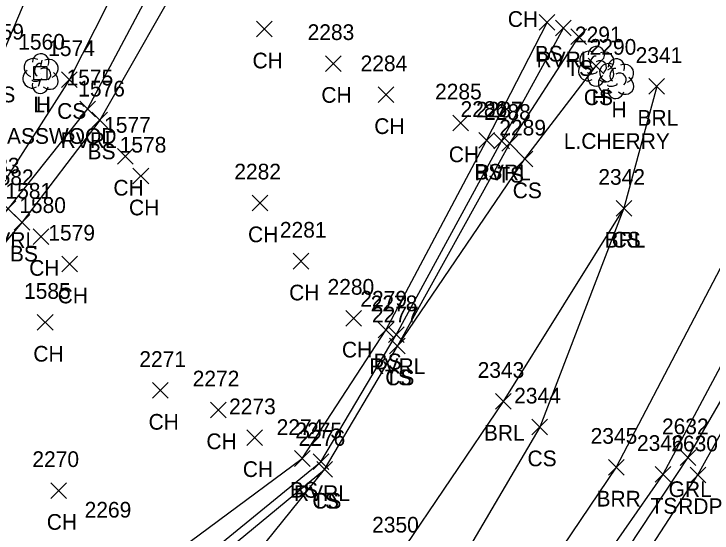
# Model space of a CAD drawing. Extents: x 1504228 to 1506103, y 437717 to 440106.
# Drawn here: x 1505331 to 1505420, y 438222.5 to 438288.7 of the extents above; entities that cross this region are included whole.
import ezdxf

# ---------------------------------------------------------------- set-up
doc = ezdxf.new("R2010")
doc.units = 0
for name, color, linetype in [('L_A', 7, 'Continuous'), ('L_C', 7, 'Continuous'), ('L_I', 7, 'Continuous'), ('L_TIC', 7, 'Continuous'), ('LABL', 7, 'Continuous'), ('LAWE', 7, 'Continuous'), ('LELB', 7, 'Continuous'), ('LTD', 7, 'Continuous'), ('P_A', 7, 'Continuous'), ('P_I', 7, 'Continuous'), ('P_TIC', 7, 'Continuous'), ('PET', 7, 'Continuous'), ('R_A', 7, 'Continuous'), ('R_I', 7, 'Continuous'), ('R_TIC', 7, 'Continuous'), ('RGR', 7, 'Continuous'), ('U_A', 7, 'Continuous'), ('U_I', 7, 'Continuous'), ('ULP', 7, 'Continuous')]:
    doc.layers.add(name, color=color, linetype=linetype)

msp = doc.modelspace()

# ---------------------------------------------------------------- linework, layer by layer
at = {"layer": 'L_TIC'}
for points in [[(1505397.951, 438286.599), (1505399.951, 438288.599)], [(1505399.951, 438286.599), (1505397.951, 438288.599)], [(1505400.036, 438285.88), (1505402.036, 438287.88)], [(1505402.036, 438285.88), (1505400.036, 438287.88)], [(1505361.905, 438285.738), (1505363.905, 438287.738)], [(1505363.905, 438285.738), (1505361.905, 438287.738)], [(1505402.001, 438284.772), (1505404.001, 438286.772)], [(1505404.001, 438284.772), (1505402.001, 438286.772)], [(1505370.679, 438281.353), (1505372.679, 438283.353)], [(1505372.679, 438281.353), (1505370.679, 438283.353)], [(1505404.197, 438281.056), (1505406.197, 438283.056)], [(1505406.197, 438281.056), (1505404.197, 438283.056)], [(1505337.033, 438279.312), (1505339.033, 438281.312)], [(1505339.033, 438279.312), (1505337.033, 438281.312)], [(1505411.94, 438278.434), (1505413.94, 438280.434)], [(1505413.94, 438278.434), (1505411.94, 438280.434)], [(1505377.43, 438277.375), (1505379.43, 438279.375)], [(1505379.43, 438277.375), (1505377.43, 438279.375)], [(1505339.369, 438275.571), (1505341.369, 438277.571)], [(1505341.369, 438275.571), (1505339.369, 438277.571)], [(1505340.915, 438274.153), (1505342.915, 438276.153)], [(1505342.915, 438274.153), (1505340.915, 438276.153)], [(1505386.933, 438273.784), (1505388.933, 438275.784)], [(1505388.933, 438273.784), (1505386.933, 438275.784)], [(1505390.234, 438271.553), (1505392.234, 438273.553)], [(1505392.234, 438271.553), (1505390.234, 438273.553)], [(1505392.16, 438271.478), (1505394.16, 438273.478)], [(1505394.16, 438271.478), (1505392.16, 438273.478)], [(1505393.187, 438271.178), (1505395.187, 438273.178)], [(1505395.187, 438271.178), (1505393.187, 438273.178)], [(1505344.162, 438269.531), (1505346.162, 438271.531)], [(1505346.162, 438269.531), (1505344.162, 438271.531)], [(1505395.131, 438269.191), (1505397.131, 438271.191)], [(1505397.131, 438269.191), (1505395.131, 438271.191)], [(1505346.151, 438267.009), (1505348.151, 438269.009)], [(1505348.151, 438267.009), (1505346.151, 438269.009)], [(1505329.226, 438262.864), (1505331.226, 438264.864)], [(1505331.226, 438262.864), (1505329.226, 438264.864)], [(1505361.331, 438263.585), (1505363.331, 438265.585)], [(1505363.331, 438263.585), (1505361.331, 438265.585)], [(1505407.751, 438262.902), (1505409.751, 438264.902)], [(1505409.751, 438262.902), (1505407.751, 438264.902)], [(1505407.751, 438262.902), (1505409.751, 438264.902)], [(1505409.751, 438262.902), (1505407.751, 438264.902)], [(1505331.016, 438261.134), (1505333.016, 438263.134)], [(1505333.016, 438261.134), (1505331.016, 438263.134)], [(1505333.424, 438259.308), (1505335.424, 438261.308)], [(1505335.424, 438259.308), (1505333.424, 438261.308)], [(1505337.055, 438255.79), (1505339.055, 438257.79)], [(1505339.055, 438255.79), (1505337.055, 438257.79)], [(1505366.575, 438256.169), (1505368.575, 438258.169)], [(1505368.575, 438256.169), (1505366.575, 438258.169)], [(1505373.306, 438248.895), (1505375.306, 438250.895)], [(1505375.306, 438248.895), (1505373.306, 438250.895)], [(1505333.952, 438248.367), (1505335.952, 438250.367)], [(1505335.952, 438248.367), (1505333.952, 438250.367)], [(1505377.412, 438247.378), (1505379.412, 438249.378)], [(1505379.412, 438247.378), (1505377.412, 438249.378)], [(1505378.725, 438246.791), (1505380.725, 438248.791)], [(1505380.725, 438246.791), (1505378.725, 438248.791)], [(1505378.879, 438245.354), (1505380.879, 438247.354)], [(1505380.879, 438245.354), (1505378.879, 438247.354)], [(1505378.879, 438245.354), (1505380.879, 438247.354)], [(1505380.879, 438245.354), (1505378.879, 438247.354)], [(1505348.649, 438239.693), (1505350.649, 438241.693)], [(1505350.649, 438239.693), (1505348.649, 438241.693)], [(1505392.358, 438238.3), (1505394.358, 438240.3)], [(1505394.358, 438238.3), (1505392.358, 438240.3)], [(1505356.022, 438237.209), (1505358.022, 438239.209)], [(1505358.022, 438237.209), (1505356.022, 438239.209)], [(1505397.015, 438235.03), (1505399.015, 438237.03)], [(1505399.015, 438235.03), (1505397.015, 438237.03)], [(1505360.667, 438233.664), (1505362.667, 438235.664)], [(1505362.667, 438233.664), (1505360.667, 438235.664)], [(1505366.728, 438231.021), (1505368.728, 438233.021)], [(1505368.728, 438231.021), (1505366.728, 438233.021)], [(1505369.111, 438230.602), (1505371.111, 438232.602)], [(1505371.111, 438230.602), (1505369.111, 438232.602)], [(1505406.768, 438229.9), (1505408.768, 438231.9)], [(1505408.768, 438229.9), (1505406.768, 438231.9)], [(1505369.579, 438229.634), (1505371.579, 438231.634)], [(1505371.579, 438229.634), (1505369.579, 438231.634)], [(1505369.579, 438229.634), (1505371.579, 438231.634)], [(1505371.579, 438229.634), (1505369.579, 438231.634)], [(1505412.735, 438228.989), (1505414.735, 438230.989)], [(1505414.735, 438228.989), (1505412.735, 438230.989)], [(1505335.668, 438226.936), (1505337.668, 438228.936)], [(1505337.668, 438226.936), (1505335.668, 438228.936)]]:
    msp.add_lwpolyline(points, dxfattribs=at)
at = {"layer": 'LABL'}
for points in [[(1505412.94, 438279.434), (1505408.751, 438263.902), (1505393.358, 438239.3), (1505379.992, 438219.583), (1505364.652, 438204.996), (1505342.27, 438194.948), (1505325.182, 438184.758), (1505314.631, 438179.74), (1505312.566, 438178.307), (1505308.953, 438177.263), (1505304.583, 438176.7), (1505296.615, 438175.22), (1505299.292, 438169.398), (1505303.904, 438164.856), (1505308.252, 438160.874), (1505313.047, 438161.473), (1505317.495, 438164.603), (1505327.49, 438169.4), (1505342.058, 438174.403)], [(1505426.709, 438267.128), (1505407.768, 438230.9), (1505394.085, 438210.643), (1505390.776, 438201.917), (1505383.002, 438197.122), (1505370.464, 438191.891), (1505357.673, 438183.248), (1505342.058, 438174.403)]]:
    msp.add_lwpolyline(points, dxfattribs=at)
at = {"layer": 'LAWE'}
for points in [[(1505362.196, 438317.813), (1505351.384, 438297.395), (1505340.369, 438276.571), (1505330.226, 438263.864), (1505321.774, 438253.978), (1505312.194, 438244.278), (1505304.566, 438239.011), (1505294.241, 438232.21), (1505286.327, 438227.151), (1505272.047, 438220.927), (1505261.327, 438215.137), (1505255.057, 438211.857), (1505252.998, 438208.079)], [(1505329.815, 438205.572), (1505347.823, 438213.433), (1505370.111, 438231.602), (1505379.725, 438247.791), (1505393.16, 438272.478), (1505401.036, 438286.88)]]:
    msp.add_lwpolyline(points, dxfattribs=at)
at = {"layer": 'LELB'}
for points in [[(1505357.525, 438320.193), (1505347.775, 438299.58), (1505338.033, 438280.312), (1505328.434, 438265.347), (1505321.109, 438255.57), (1505311.747, 438245.782), (1505304.42, 438239.919), (1505293.736, 438234.076), (1505284.045, 438228.619), (1505270.947, 438221.02), (1505260.492, 438217.948), (1505254.014, 438216.283), (1505247.096, 438215.294)], [(1505270.798, 438231.377), (1505288.172, 438238.832), (1505306.017, 438251.366), (1505315.372, 438266.647), (1505328.992, 438282.411), (1505336.428, 438299.931), (1505351.563, 438320.448)], [(1505365.146, 438316.099), (1505353.966, 438296.236), (1505341.915, 438275.153), (1505332.016, 438262.134), (1505323.954, 438252.628), (1505313.563, 438242.629), (1505305.646, 438236.558), (1505295.746, 438229.78), (1505286.64, 438224.685), (1505273.677, 438216.738), (1505262.485, 438213.279), (1505253.251, 438208.207), (1505250.962, 438202.759), (1505231.919, 438194.06), (1505223.449, 438190.476), (1505215.829, 438187.003), (1505207.689, 438183.331), (1505196.859, 438178.456)], [(1505258.116, 438181.066), (1505268.339, 438182.172), (1505278.498, 438189.358), (1505293.602, 438192.608), (1505306.445, 438196.96), (1505314.273, 438197.344), (1505329.9, 438207.293), (1505346.396, 438216.217), (1505367.728, 438232.021), (1505378.412, 438248.378), (1505391.234, 438272.553), (1505398.951, 438287.599)], [(1505287.419, 438180.921), (1505294.194, 438184.889), (1505305.914, 438191.586), (1505317.977, 438192.973), (1505331.239, 438203.009), (1505347.587, 438211.637), (1505370.579, 438230.634), (1505379.879, 438246.354), (1505394.187, 438272.178), (1505403.001, 438285.772)], [(1505379.879, 438246.354), (1505396.131, 438270.191), (1505405.197, 438282.056)], [(1505433.081, 438266.273), (1505413.735, 438229.989), (1505398.795, 438208.567), (1505392.864, 438200.506)], [(1505408.751, 438263.902), (1505398.015, 438236.03), (1505385.067, 438213.947), (1505364.652, 438204.996), (1505348.803, 438190.971), (1505327.848, 438180.889), (1505316.341, 438173.385)], [(1505306.221, 438188.545), (1505319.546, 438190.519), (1505334.224, 438198.941), (1505350.38, 438205.602), (1505370.579, 438230.634)]]:
    msp.add_lwpolyline(points, dxfattribs=at)
at = {"layer": 'LTD'}
for p, q in [((1505405.197, 438282.056), (1505405.197, 438282.056)), ((1505405.197, 438282.056), (1505405.197, 438282.056)), ((1505334.342, 438281.123), (1505334.342, 438281.123)), ((1505334.342, 438281.123), (1505334.342, 438281.123)), ((1505407.73, 438280.478), (1505407.73, 438280.478)), ((1505407.73, 438280.478), (1505407.73, 438280.478))]:
    msp.add_line(p, q, dxfattribs=at)
for centre in [(1505405.244, 438283.49), (1505334.389, 438282.557), (1505407.777, 438281.912)]:
    msp.add_arc(centre, 1.047, 335.52715, 180.95627, dxfattribs=at)
for centre, major_axis, ratio, start_param, end_param in [((1505404.405, 438282.723), (1.21, -0.512), 0.895232, 1.570796, 4.712389), ((1505406.239, 438282.64), (-1.141, -0.483), 0.949671, 1.570796, 4.712389), ((1505333.551, 438281.789), (1.21, -0.512), 0.895232, 1.570796, 4.712389), ((1505335.384, 438281.706), (-1.141, -0.483), 0.949671, 1.570796, 4.712389), ((1505404.989, 438282.515), (-0.208, -0.792), 0.645439, 3.141593, 6.283185), ((1505405.697, 438281.89), (-0.5, 0.667), 0.989748, 3.141593, 6.283185), ((1505334.134, 438281.581), (-0.208, -0.792), 0.645439, 3.141593, 6.283185), ((1505334.842, 438280.956), (-0.5, 0.667), 0.989748, 3.141593, 6.283185), ((1505404.114, 438281.348), (0.584, -1.042), 0.959034, 3.141593, 6.283185), ((1505406.938, 438281.145), (1.21, -0.512), 0.895232, 1.570796, 4.712389), ((1505406.197, 438281.223), (-1.09, 0.792), 0.841452, 1.570796, 4.712389), ((1505407.521, 438280.937), (-0.208, -0.792), 0.645439, 3.141593, 6.283185), ((1505408.771, 438281.062), (-1.141, -0.483), 0.949671, 1.570796, 4.712389), ((1505333.259, 438280.414), (0.584, -1.042), 0.959034, 3.141593, 6.283185), ((1505335.343, 438280.289), (-1.09, 0.792), 0.841452, 1.570796, 4.712389), ((1505405.197, 438280.556), (0.265, 1.061), 0.942809, 1.570796, 4.712389), ((1505404.739, 438281.306), (-0.625, -0.083), 0.423636, 0, 3.141593), ((1505406.647, 438279.77), (0.584, -1.042), 0.959034, 3.141593, 6.283185), ((1505408.23, 438280.312), (-0.5, 0.667), 0.989748, 3.141593, 6.283185), ((1505334.343, 438279.623), (0.265, 1.061), 0.942809, 1.570796, 4.712389), ((1505333.884, 438280.373), (-0.625, -0.083), 0.423636, 0, 3.141593), ((1505408.73, 438279.645), (-1.09, 0.792), 0.841452, 1.570796, 4.712389), ((1505407.73, 438278.978), (0.265, 1.061), 0.942809, 1.570796, 4.712389), ((1505407.272, 438279.728), (-0.625, -0.083), 0.423636, 0, 3.141593)]:
    msp.add_ellipse(centre, major_axis=major_axis, ratio=ratio, start_param=start_param, end_param=end_param, dxfattribs=at)
at = {"layer": 'P_TIC'}
for points in [[(1505417.189, 438228.936), (1505419.189, 438230.936)], [(1505419.189, 438228.936), (1505417.189, 438230.936)]]:
    msp.add_lwpolyline(points, dxfattribs=at)
at = {"layer": 'PET'}
msp.add_lwpolyline([(1505311.676, 438134.175), (1505324.098, 438128.725), (1505335.82, 438133.23), (1505344.252, 438137.011), (1505351.761, 438143.58), (1505369.207, 438162.724), (1505390.677, 438190.218), (1505407.619, 438213.727), (1505418.189, 438229.936), (1505438.053, 438265.664)], dxfattribs=at)
at = {"layer": 'R_TIC'}
for points in [[(1505415.914, 438231.111), (1505417.914, 438233.111)], [(1505417.914, 438231.111), (1505415.914, 438233.111)]]:
    msp.add_lwpolyline(points, dxfattribs=at)
at = {"layer": 'RGR'}
msp.add_lwpolyline([(1505381.79, 438190.333), (1505384.268, 438190.42), (1505390.057, 438193.61), (1505404.907, 438213.977), (1505416.914, 438232.111), (1505436.312, 438265.645)], dxfattribs=at)
at = {"layer": 'ULP'}
for p, q in [((1505334.509, 438282.789), (1505334.342, 438281.956)), ((1505333.509, 438280.289), (1505333.509, 438281.956)), ((1505333.509, 438281.956), (1505335.176, 438281.956)), ((1505335.176, 438281.956), (1505335.176, 438280.289)), ((1505334.342, 438281.123), (1505334.342, 438281.123)), ((1505335.176, 438280.289), (1505333.509, 438280.289)), ((1505334.092, 438279.456), (1505334.342, 438280.289))]:
    msp.add_line(p, q, dxfattribs=at)

# ---------------------------------------------------------------- texts
at = {"layer": 'L_A'}
for s, p in [('CH', (1505393.946, 438287.025)), ('BS', (1505397.392, 438282.599)), ('CH', (1505361.393, 438281.738)), ('RVRL', (1505397.603, 438281.88)), ('TS', (1505401.411, 438280.772)), ('CS', (1505327.433, 438277.411)), ('CH', (1505370.167, 438277.353)), ('CS', (1505403.638, 438277.056)), ('H', (1505404.63, 438277.056)), ('H', (1505333.776, 438276.123)), ('CS', (1505336.474, 438275.312)), ('H', (1505407.163, 438275.478)), ('BRL', (1505410.483, 438274.434)), ('CH', (1505376.918, 438273.375)), ('RVRL', (1505336.936, 438271.571)), ('BS', (1505340.356, 438270.153)), ('CH', (1505386.421, 438269.784)), ('BS', (1505389.675, 438267.553)), ('RVRL', (1505389.727, 438267.478)), ('TS', (1505392.596, 438267.178)), ('CH', (1505343.65, 438265.531)), ('CS', (1505394.572, 438265.191)), ('CH', (1505345.64, 438263.009)), ('CH', (1505360.819, 438259.585)), ('RVRL', (1505326.793, 438258.864)), ('BRL', (1505406.294, 438258.902)), ('CS', (1505407.192, 438258.902)), ('BS', (1505330.457, 438257.134)), ('CH', (1505332.912, 438255.308)), ('CH', (1505366.063, 438252.169)), ('CH', (1505336.543, 438251.79)), ('CH', (1505372.794, 438244.895)), ('CH', (1505333.441, 438244.367)), ('BS', (1505376.853, 438243.378)), ('RVRL', (1505376.292, 438242.791)), ('TS', (1505378.288, 438241.354)), ('CS', (1505378.32, 438241.354)), ('CH', (1505348.138, 438235.693)), ('BRL', (1505390.901, 438234.3)), ('CH', (1505355.51, 438233.209)), ('CS', (1505396.456, 438231.03)), ('CH', (1505360.155, 438229.664)), ('BS', (1505366.169, 438227.021)), ('RVRL', (1505366.678, 438226.602)), ('TS', (1505368.988, 438225.634)), ('CS', (1505369.02, 438225.634)), ('BRR', (1505405.256, 438225.9)), ('TS', (1505412.144, 438224.989)), ('CH', (1505335.156, 438222.936))]:
    msp.add_text(s, height=2, dxfattribs=at).set_placement(p)
at = {"layer": 'L_C'}
for s, p in [('M.BASSWOOD', (1505325.327, 438272.123)), ('L.CHERRY', (1505401.084, 438271.478))]:
    msp.add_text(s, height=2, dxfattribs=at).set_placement(p)
at = {"layer": 'L_I'}
for s, p in [('1559', (1505326.291, 438285.411)), ('2283', (1505368.419, 438285.353)), ('2291', (1505402.504, 438285.056)), ('2291', (1505402.504, 438285.056)), ('1560', (1505331.516, 438284.123)), ('1574', (1505335.34, 438283.312)), ('2290', (1505404.383, 438283.478)), ('2341', (1505410.247, 438282.434)), ('2284', (1505375.17, 438281.375)), ('1575', (1505337.676, 438279.571)), ('1576', (1505339.167, 438278.153)), ('2285', (1505384.673, 438277.784)), ('2286', (1505387.919, 438275.553)), ('2287', (1505389.9, 438275.478)), ('2288', (1505390.927, 438275.178)), ('1577', (1505342.469, 438273.531)), ('2289', (1505392.863, 438273.191)), ('1578', (1505344.458, 438271.009)), ('1583', (1505325.741, 438268.347)), ('2282', (1505359.071, 438267.585)), ('1582', (1505327.533, 438266.864)), ('2342', (1505405.491, 438266.902)), ('2342', (1505405.491, 438266.902)), ('1581', (1505329.89, 438265.134)), ('1580', (1505331.645, 438263.308)), ('2281', (1505364.882, 438260.169)), ('1579', (1505335.354, 438259.79)), ('1585', (1505332.259, 438252.367)), ('2280', (1505370.96, 438252.895)), ('2279', (1505375.145, 438251.378)), ('2278', (1505376.465, 438250.791)), ('2277', (1505376.619, 438249.354)), ('2277', (1505376.619, 438249.354)), ('2271', (1505346.957, 438243.693)), ('2343', (1505390.098, 438242.3)), ('2272', (1505353.762, 438241.209)), ('2344', (1505394.755, 438239.03)), ('2273', (1505358.407, 438237.664)), ('2274', (1505364.468, 438235.021)), ('2275', (1505366.851, 438234.602)), ('2276', (1505367.264, 438233.634)), ('2276', (1505367.264, 438233.634)), ('2345', (1505404.508, 438233.9)), ('2346', (1505410.42, 438232.989)), ('2270', (1505333.321, 438230.936)), ('2269', (1505339.984, 438224.489)), ('2350', (1505376.645, 438222.583))]:
    msp.add_text(s, height=2, dxfattribs=at).set_placement(p)
at = {"layer": 'P_A'}
msp.add_text('RDP', height=2, dxfattribs=at).set_placement((1505415.677, 438224.936))
at = {"layer": 'P_I'}
msp.add_text('2630', height=2, dxfattribs=at).set_placement((1505414.795, 438232.936))
at = {"layer": 'R_A'}
msp.add_text('GRL', height=2, dxfattribs=at).set_placement((1505414.458, 438227.111))
at = {"layer": 'R_I'}
msp.add_text('2632', height=2, dxfattribs=at).set_placement((1505413.607, 438235.111))
at = {"layer": 'U_A'}
msp.add_text('LI', height=2, dxfattribs=at).set_placement((1505333.445, 438276.123))
at = {"layer": 'U_I'}
msp.add_text('1560', height=2, dxfattribs=at).set_placement((1505331.516, 438284.123))

doc.saveas('drawing.dxf')
